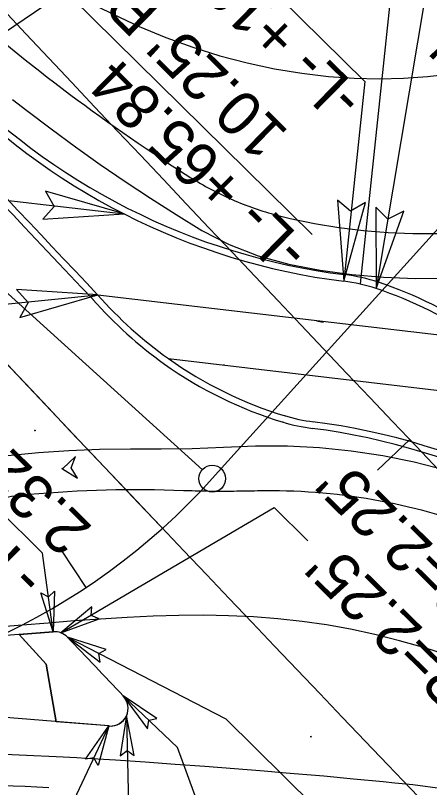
# Model space of a CAD drawing. Extents: x 1262642 to 1268358, y 767825 to 773481.
# Drawn here: x 1266748.8 to 1266795.4, y 772119 to 772205.7 of the extents above; entities that cross this region are included whole.
import ezdxf

# ---------------------------------------------------------------- set-up
doc = ezdxf.new("R2010")
doc.units = 0
for name, color, linetype in [('Prop Conc 1ft 6in Curb and Gutter', 7, 'Continuous'), ('Prop Conc 2ft 6in Curb and Gutter', 7, 'Continuous'), ('Prop Conc 5in Monolithic Keyed In Island', 7, 'Continuous'), ('Prop Dimension', 7, 'Continuous'), ('Prop Dimension Text', 7, 'Continuous'), ('Prop EOT', 7, 'Continuous'), ('Prop Horizontal Alignment', 7, 'Continuous'), ('Prop Horizontal Alignment Station Label', 7, 'Continuous'), ('Prop Horizontal Alignment Tick Small', 7, 'Continuous'), ('Prop Lane Lines', 7, 'Continuous'), ('Prop Shade Medium', 7, 'Continuous'), ('Prop Terminator CELL', 7, 'Continuous'), ('Scratch_Level_3', 7, 'Continuous')]:
    doc.layers.add(name, color=color, linetype=linetype)

msp = doc.modelspace()

# ---------------------------------------------------------------- linework, layer by layer
at = {"layer": 'Prop Conc 1ft 6in Curb and Gutter'}
for p, q in [((1266749.568, 772135.859), (1266752.285, 772132.888)), ((1266752.285, 772132.888), (1266753.411, 772126.424))]:
    msp.add_line(p, q, dxfattribs=at)
at = {"layer": 'Prop Conc 2ft 6in Curb and Gutter'}
for p, q in [((1266800.905, 772169.279), (1266758.086, 772174.32)), ((1266782.632, 772171.431), (1266783.413, 772171.268)), ((1266783.413, 772171.268), (1266783.438, 772171.336)), ((1266766.008, 772167.185), (1266808.991, 772162.125))]:
    msp.add_line(p, q, dxfattribs=at)
for centre, radius, start, end in [((1266793.506, 772205.681), 47.309, 221.52104, 234.4606), ((1266772.205, 772166.198), 0.268, 65.77713, 100.79472)]:
    msp.add_arc(centre, radius, start, end, dxfattribs=at)
at = {"layer": 'Prop Conc 5in Monolithic Keyed In Island'}
for p, q in [((1266800.905, 772169.279), (1266758.086, 772174.32)), ((1266766.008, 772167.185), (1266808.991, 772162.125)), ((1266753.061, 772136.521), (1266731.75, 772134.826)), ((1266749.24, 772136.217), (1266752.285, 772132.888)), ((1266753.411, 772126.424), (1266752.285, 772132.888)), ((1266759.327, 772125.948), (1266722.896, 772128.884))]:
    msp.add_line(p, q, dxfattribs=at)
for centre, radius, start, end in [((1275047.307, 780021.225), 11414.25, 222.8297896, 223.4298287), ((1266795.008, 772250.288), 75, 223.27927, 262.87792), ((1266783.323, 772156.765), 19.25, 71.69984, 82.87792), ((1266775.238, 772132.318), 45, 55.22254, 71.69984), ((1266793.506, 772205.681), 47.309, 221.52104, 234.4606), ((1266792.096, 772203.851), 45, 234.56812, 253.24921), ((1266784.674, 772179.194), 19.25, 252.9976, 262.96775), ((1266772.773, 772085.698), 75, 43.80193, 82.74583), ((1266753.22, 772134.527), 2, 43.55465, 94.54789), ((1275046.886, 780019.972), 11442, 223.5546546, 223.6001726), ((1266759.487, 772127.941), 2, 265.39188, 43.60017)]:
    msp.add_arc(centre, radius, start, end, dxfattribs=at)
at = {"layer": 'Prop Dimension'}
for p, q in [((1266753.907, 772136.393), (1266777.888, 772150.474)), ((1266753.061, 772136.521), (1266751.861, 772145.344)), ((1266754.67, 772135.906), (1266772.475, 772126.743)), ((1266760.936, 772129.32), (1266767.033, 772123.516)), ((1266761.302, 772127.127), (1266762.342, 772082.502)), ((1266759.327, 772125.948), (1266715.462, 772033.189))]:
    msp.add_line(p, q, dxfattribs=at)
at = {"layer": 'Prop Dimension Text'}
for p, q in [((1266761.492, 772224.482), (1266788.074, 772198.292)), ((1266754.434, 772208.43), (1266782.15, 772181.121)), ((1266751.861, 772145.344), (1266725.28, 772171.535)), ((1266777.888, 772150.474), (1266781.687, 772146.731)), ((1266820.023, 772079.893), (1266772.475, 772126.743)), ((1266791.444, 772057.149), (1266767.033, 772123.516))]:
    msp.add_line(p, q, dxfattribs=at)
for points in [[(1266797.725, 772224.805), (1266789.373, 772175.059)], [(1266791.406, 772212.084), (1266787.561, 772175.561)], [(1266754.434, 772208.43), (1266740.368, 772198.877)], [(1266788.074, 772198.292), (1266785.71, 772175.867)], [(1266740.875, 772185.77), (1266761.026, 772183.425)], [(1266737.577, 772172.272), (1266758.096, 772174.335)]]:
    msp.add_lwpolyline(points, dxfattribs=at)
at = {"layer": 'Prop EOT'}
for centre, radius, start, end in [((1275047.307, 780021.225), 11415, 222.8297896, 223.4298287), ((1266795.008, 772250.288), 74.25, 223.27927, 262.87792), ((1266783.323, 772156.765), 20, 71.69984, 82.87792), ((1266775.238, 772132.318), 45.75, 55.22254, 71.69984), ((1266793.506, 772205.681), 48.059, 221.52104, 234.4606), ((1266792.096, 772203.851), 45.75, 234.56812, 253.24921), ((1266784.674, 772179.194), 20, 252.9976, 262.96775), ((1266772.773, 772085.698), 74.25, 43.80193, 82.74583)]:
    msp.add_arc(centre, radius, start, end, dxfattribs=at)
at = {"layer": 'Prop Horizontal Alignment'}
msp.add_line((1266770.936, 772153.71), (1267443.049, 772897.651), dxfattribs=at)
for centre, radius, start, end in [((1275047.307, 780021.225), 11400, 222.9935866, 225.4043192), ((1266715.285, 772203.988), 75, 223.23333, 317.90382)]:
    msp.add_arc(centre, radius, start, end, dxfattribs=at)
at = {"layer": 'Prop Horizontal Alignment Station Label'}
msp.add_line((1266769.823, 772154.715), (1266566.881, 772338.064), dxfattribs=at)
msp.add_circle((1266770.936, 772153.71), 1.5, dxfattribs=at)
at = {"layer": 'Prop Horizontal Alignment Tick Small'}
for p, q in [((1266793.142, 772158.098), (1266789.522, 772154.65)), ((1266756.768, 772141.505), (1266754.003, 772145.671))]:
    msp.add_line(p, q, dxfattribs=at)
at = {"layer": 'Prop Lane Lines'}
for start, end in [(216.3674993, 223.5476842), (222.9935866, 225.3637298)]:
    msp.add_arc((1275047.307, 780021.225), 11427, start, end, dxfattribs=at)
at = {"layer": 'Prop Shade Medium'}
for p, q in [((1266800.905, 772169.279), (1266758.086, 772174.32)), ((1266766.008, 772167.185), (1266808.991, 772162.125)), ((1266779.045, 772160.785), (1266779.126, 772160.761)), ((1266749.24, 772136.217), (1266753.061, 772136.521)), ((1266752.285, 772132.888), (1266749.24, 772136.217)), ((1266753.411, 772126.424), (1266752.285, 772132.888)), ((1266759.327, 772125.948), (1266753.411, 772126.424)), ((1266759.375, 772125.944), (1266759.327, 772125.948))]:
    msp.add_line(p, q, dxfattribs=at)
for centre, radius, start, end in [((1275047.307, 780021.225), 11414.25, 222.8297896, 223.4298287), ((1266795.008, 772250.288), 75, 223.27927, 262.87792), ((1266783.323, 772156.765), 19.25, 71.69984, 82.87792), ((1266775.238, 772132.318), 45, 55.22254, 71.69984), ((1266792.096, 772203.851), 45, 234.56812, 253.24921), ((1266784.674, 772179.194), 19.25, 252.9976, 262.96775), ((1266772.773, 772085.698), 75, 43.80193, 82.74583), ((1266753.22, 772134.527), 2, 43.55465, 94.54789), ((1275046.886, 780019.972), 11442, 223.5546546, 223.6001726), ((1266759.487, 772127.941), 2, 266.78605, 43.60017)]:
    msp.add_arc(centre, radius, start, end, dxfattribs=at)
at = {"layer": 'Prop Terminator CELL'}
for points in [[(1266751.912, 772182.842), (1266761.026, 772183.425), (1266752.197, 772185.979), (1266753.17, 772184.266)], [(1266785.028, 772184.974), (1266785.71, 772175.867), (1266788.168, 772184.722), (1266786.466, 772183.73)], [(1266789.334, 772184.191), (1266789.373, 772175.059), (1266792.449, 772183.719), (1266790.681, 772182.85)], [(1266749.319, 772171.812), (1266758.096, 772174.335), (1266748.925, 772174.937), (1266750.243, 772173.472)], [(1266753.224, 772141.084), (1266753.061, 772136.521), (1266751.66, 772140.897), (1266752.53, 772140.435)], [(1266757.42, 772139.31), (1266753.907, 772136.393), (1266758.228, 772137.958), (1266757.33, 772138.364)], [(1266759.025, 772134.536), (1266754.67, 772135.906), (1266758.327, 772133.124), (1266758.182, 772134.098)], [(1266764.729, 772126.779), (1266760.936, 772129.32), (1266763.661, 772125.621), (1266763.796, 772126.597)], [(1266762.181, 772122.646), (1266761.302, 772127.127), (1266760.607, 772122.584), (1266761.394, 772123.178)], [(1266756.702, 772122.211), (1266759.327, 772125.948), (1266758.115, 772121.515), (1266757.638, 772122.377)]]:
    msp.add_lwpolyline(points, close=True, dxfattribs=at)
at = {"layer": 'Scratch_Level_3'}
for points in [[(1266758.054, 772206.709), (1266759.789, 772205.836), (1266762.724, 772204.476), (1266765.71, 772203.241), (1266768.74, 772202.14), (1266771.799, 772201.18), (1266774.867, 772200.369), (1266777.932, 772199.711), (1266780.996, 772199.204), (1266783.988, 772198.853), (1266786.887, 772198.651), (1266789.688, 772198.586), (1266792.42, 772198.647), (1266795.121, 772198.831), (1266797.787, 772199.135), (1266800.414, 772199.559), (1266803.004, 772200.1), (1266805.549, 772200.756), (1266808.059, 772201.531), (1266810.499, 772202.411), (1266812.883, 772203.399), (1266815.228, 772204.498), (1266815.459, 772204.613)], [(1266748.494, 772196.274), (1266750.108, 772195.021), (1266752.825, 772192.967), (1266755.573, 772190.956), (1266758.353, 772188.988), (1266761.164, 772187.064), (1266764.004, 772185.184), (1266766.874, 772183.349), (1266769.78, 772181.571), (1266772.846, 772180.001), (1266776.103, 772178.723), (1266779.535, 772177.787), (1266783.056, 772177.117), (1266786.607, 772176.625), (1266790.178, 772176.311), (1266793.761, 772176.178), (1266797.345, 772176.224), (1266800.923, 772176.45), (1266804.486, 772176.855), (1266808.023, 772177.439), (1266811.527, 772178.196), (1266814.996, 772179.071), (1266815.341, 772179.168)], [(1266767.906, 772187.883), (1266768.187, 772187.704), (1266768.469, 772187.527), (1266768.753, 772187.352), (1266769.038, 772187.179), (1266769.325, 772187.009), (1266769.613, 772186.841), (1266769.902, 772186.676), (1266770.193, 772186.513), (1266770.485, 772186.352), (1266770.779, 772186.194), (1266771.074, 772186.039), (1266771.37, 772185.887), (1266771.668, 772185.737), (1266771.967, 772185.589), (1266772.267, 772185.445), (1266772.569, 772185.303), (1266772.872, 772185.165), (1266773.176, 772185.029), (1266773.482, 772184.896), (1266773.789, 772184.766), (1266774.097, 772184.639), (1266774.407, 772184.515), (1266774.718, 772184.395), (1266775.03, 772184.277), (1266775.343, 772184.163), (1266775.657, 772184.052), (1266775.972, 772183.944), (1266776.289, 772183.84), (1266776.607, 772183.739), (1266776.926, 772183.642), (1266777.245, 772183.548), (1266777.566, 772183.457), (1266777.888, 772183.37)], [(1266810.921, 772147.927), (1266809.834, 772148.75), (1266806.958, 772150.648), (1266803.86, 772152.275), (1266800.55, 772153.584), (1266797.116, 772154.652), (1266793.633, 772155.548), (1266790.109, 772156.268), (1266786.554, 772156.812), (1266782.975, 772157.177), (1266779.383, 772157.363), (1266775.786, 772157.37), (1266772.199, 772157.207), (1266768.664, 772157.055), (1266765.183, 772157.013), (1266761.734, 772157.034), (1266758.285, 772156.973), (1266754.839, 772156.827), (1266751.398, 772156.596), (1266747.963, 772156.28), (1266747.277, 772156.207)], [(1266776.028, 772152.329), (1266775.695, 772152.321), (1266775.361, 772152.315), (1266775.028, 772152.308), (1266774.695, 772152.302), (1266774.362, 772152.297), (1266774.028, 772152.292), (1266773.695, 772152.288), (1266773.362, 772152.285), (1266773.028, 772152.282), (1266772.695, 772152.28), (1266772.362, 772152.279), (1266772.028, 772152.278), (1266771.695, 772152.279), (1266771.362, 772152.28), (1266771.028, 772152.282), (1266770.695, 772152.285), (1266770.362, 772152.289), (1266770.028, 772152.294), (1266769.695, 772152.3), (1266769.362, 772152.307), (1266769.029, 772152.315), (1266768.695, 772152.324), (1266768.362, 772152.335), (1266768.029, 772152.346), (1266767.696, 772152.359)], [(1266750.363, 772151.914), (1266750.031, 772151.884), (1266749.699, 772151.851), (1266749.367, 772151.815), (1266749.036, 772151.776), (1266748.706, 772151.734), (1266748.375, 772151.689), (1266748.045, 772151.641), (1266747.716, 772151.59), (1266747.387, 772151.536), (1266747.059, 772151.479), (1266746.731, 772151.419), (1266746.404, 772151.355), (1266746.077, 772151.288), (1266745.751, 772151.218), (1266745.426, 772151.144), (1266745.102, 772151.067), (1266744.778, 772150.987), (1266744.456, 772150.903), (1266744.134, 772150.816), (1266743.813, 772150.726), (1266743.493, 772150.632), (1266743.174, 772150.535), (1266742.857, 772150.434)], [(1266798.928, 772133.354), (1266797.743, 772133.766), (1266794.83, 772134.705), (1266791.981, 772135.521), (1266789.217, 772136.214), (1266786.485, 772136.802), (1266783.759, 772137.291), (1266781.042, 772137.682), (1266778.316, 772137.981), (1266775.562, 772138.192), (1266772.773, 772138.32), (1266769.983, 772138.369), (1266767.182, 772138.349), (1266764.317, 772138.266), (1266761.377, 772138.127), (1266758.385, 772137.943), (1266755.42, 772137.732), (1266752.487, 772137.495), (1266749.6, 772137.263), (1266746.721, 772137.048), (1266746.147, 772137.008)], [(1266718.312, 772124.183), (1266720.55, 772124.073), (1266723.749, 772123.92), (1266726.947, 772123.767), (1266730.147, 772123.615), (1266733.409, 772123.461), (1266736.736, 772123.303), (1266740.068, 772123.154), (1266743.4, 772122.999), (1266746.732, 772122.832), (1266750.064, 772122.676), (1266753.396, 772122.519), (1266755.728, 772122.409)], [(1266755.728, 772122.409), (1266756.729, 772122.354), (1266760.073, 772122.141), (1266763.417, 772121.917), (1266766.76, 772121.681), (1266770.102, 772121.434), (1266773.444, 772121.175), (1266776.784, 772120.905), (1266778.788, 772120.738)], [(1266778.788, 772120.738), (1266780.124, 772120.624), (1266783.467, 772120.361), (1266786.8, 772120.027), (1266790.136, 772119.711), (1266791.47, 772119.581)], [(1266791.47, 772119.581), (1266793.471, 772119.384), (1266796.813, 772118.932), (1266800.167, 772118.113), (1266803.488, 772116.893), (1266806.745, 772115.46), (1266809.921, 772113.856), (1266813.009, 772112.086), (1266815.998, 772110.154), (1266818.826, 772107.988), (1266821.493, 772105.617), (1266824.007, 772103.084), (1266826.363, 772100.399), (1266828.673, 772097.733), (1266831.034, 772095.229), (1266833.472, 772092.899), (1266833.96, 772092.435)]]:
    msp.add_lwpolyline(points, dxfattribs=at)
msp.add_lwpolyline([(1266754.102, 772154.828), (1266755.792, 772153.758), (1266755.098, 772154.918), (1266755.573, 772156.183)], close=True, dxfattribs=at)
for centre in [(1266751.017, 772159.121), (1266751.017, 772159.121), (1266754.102, 772154.828), (1266754.102, 772154.828), (1266782.029, 772124.746), (1266782.029, 772124.746)]:
    msp.add_circle(centre, 0.0417, dxfattribs=at)
for centre, radius, start, end in [((1266882.309, 772367.05), 212.577, 228.35539, 237.4405), ((1266794.626, 772247.573), 66.349, 255.38768, 280.99965), ((1266762.505, 772017.013), 135.446, 87.80338, 95.14322), ((1266777.458, 772085.377), 66.967, 68.89437, 91.22346), ((1268393.275, 807244.536), 35163.78, 267.2908732, 267.3256629)]:
    msp.add_arc(centre, radius, start, end, dxfattribs=at)

# ---------------------------------------------------------------- texts
at = {"layer": 'Prop Dimension'}
for s, p in [("R=5'", (1266808.381, 772195.306)), ("R=2.25'", (1266802.18, 772140.047)), ("R=2.25'", (1266801.019, 772130.645))]:
    msp.add_text(s, height=5, rotation=135.42387, dxfattribs=at).set_placement(p)
at = {"layer": 'Prop Dimension Text'}
for s, p in [('-L- +18.00', (1266788.22, 772196.725)), ("10.25' RT", (1266779.672, 772192.586)), ('-L- +65.84', (1266782.145, 772179.62)), ('-Y38SW- +94.34', (1266752.336, 772142.872)), ("2.32' RT", (1266757.6, 772148.215))]:
    msp.add_text(s, height=5, rotation=135.42387, dxfattribs=at).set_placement(p)

doc.saveas('drawing.dxf')
